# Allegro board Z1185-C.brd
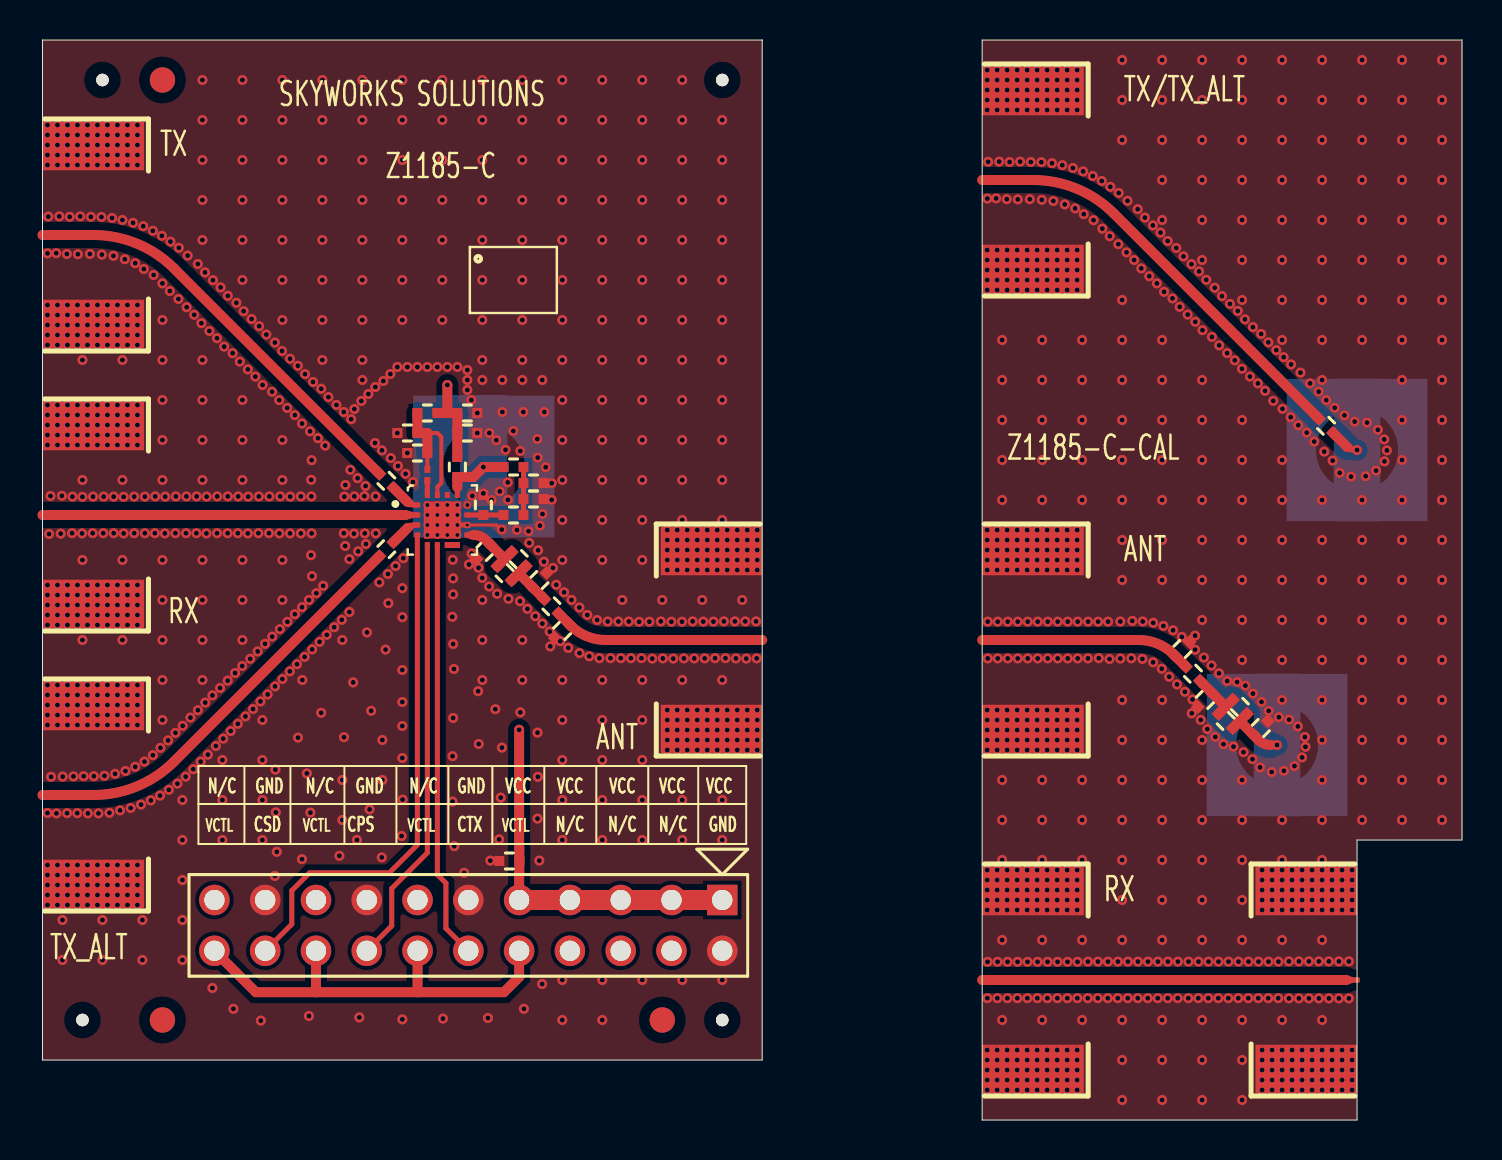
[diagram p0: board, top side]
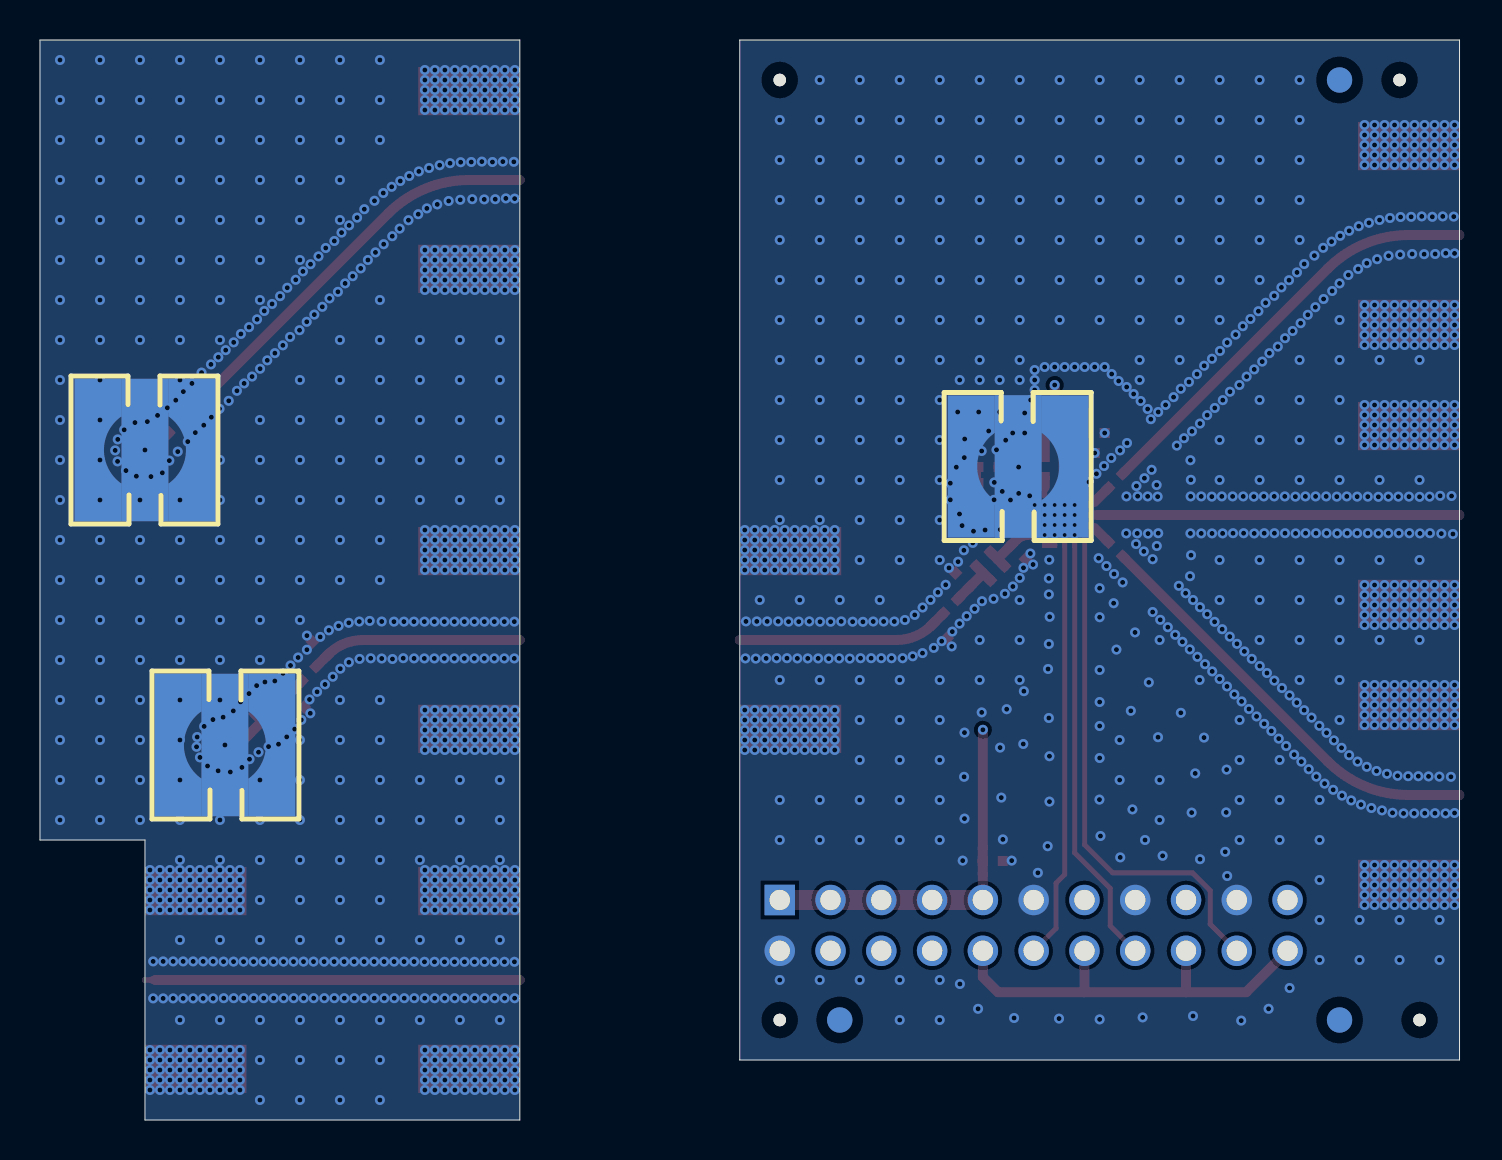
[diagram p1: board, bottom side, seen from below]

Outline 71 x 54 mm; copper layers: TOP, L2, L3, BOTTOM. Coordinates in mm from the lower left corner of the outline.
Outline path: 0,54 36,54 36,3 0,3 0,54 ; 47,54 47,0 65.75,0 65.75,14 71,14 71,54 47,54

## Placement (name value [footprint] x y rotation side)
C2  10nF  [CAP_SMD_0402_1M0MX0M5M_B]  18.25 34.35 180 top
C3  33pF  [CAP_SMD_0402_1M0MX0M5M_B]  21.25 34.35 180 top
C4  4.7uF  [CAP_SMD_0402_1M0MX0M5M_B]  23.35 12.95 0 top
C5  82pF  [CAP_SMD_0402_1M0MX0M5M_B]  18.75 33.35 180 top
C7  DNI  [CAP_SMD_0402_1M0MX0M5M_B]  24.56 31.05 0 top
C8  10pF  [CAP_SMD_0402_1M0MX0M5M_B]  24.56 31.85 0 top
C9  2.4pF  [CAP_SMD_0402_1M0MX0M5M_B]  22.05 30.75 90 top
C10  2.2pF  [CAP_SMD_0402_1M0MX0M5M_B]  24.86 27 45 top
C11  DNI  [CAP_SMD_0402_1M0MX0M5M_B]  58.14 21 225 top
C12  DNI  [CAP_SMD_0402_1M0MX0M5M_B]  22.06 28.4 225 top
C13  DNI  [CAP_SMD_0402_1M0MX0M5M_B]  25.98 24.45 225 top
C14  1.5pF  [CAP_SMD_0402_1M0MX0M5M_B]  23.11 27.34 315 top
C15  DNI  [CAP_SMD_0402_1M0MX0M5M_B]  60.94 19.6 45 top
C16  DNI  [CAP_SMD_0402_1M0MX0M5M_B]  57.02 23.55 45 top
C17  DNI  [CAP_SMD_0402_1M0MX0M5M_B]  59.18 19.95 135 top
C18  1nF  [CAP_SMD_0402_1M0MX0M5M_B]  21.25 35.35 180 top
FB1  0R  [IND_SMD_0402_1M0MX0M5M_B]  19.25 35.35 180 top
J1  SMA  [SMA_END_B]  0 30.25 180 top
J2  SMA  [SMA_END_B]  0 44.25 180 top
J3  SMA  [SMA_END_B]  36 24 0 top
J4  DNI  [CONN_AMP_132134_10_V2]  22.08 32.67 180 bottom
J5  SMA  [SMA_END_B]  0 16.25 180 top
J6  SMA  [SMA_END_B]  47 47 180 top
J7  SMA  [SMA_END_B]  47 7 180 top
J9  AMP  [CONN_AMP_132134_10_V2]  65.75 33.5 180 bottom
J10  SMA  [SMA_END_B]  65.75 7 0 top
J12  AMP  [CONN_AMP_132134_10_V2]  61.75 18.75 0 bottom
J13  SMA  [SMA_END_B]  47 24 180 top
L1  6.8nH  [IND_SMD_0402_1M0MX0M5M_B]  20.75 32.65 270 top
L2  0.6nH  [IND_SMD_0201_0M6MX0M3M_B]  19.25 32.25 270 top
L3  2.4nH  [IND_SMD_0402_1M0MX0M5M_B]  23.56 32.65 180 top
L4  7.5nH  [IND_SMD_0402_1M0MX0M5M_B]  23.56 30.25 180 top
L5  5.6nH  [IND_SMD_0402_1M0MX0M5M_B]  23.82 28.05 135 top
L6  5.6nH  [IND_SMD_0402_1M0MX0M5M_B]  25.46 25.68 135 top
L7  DNI  [IND_SMD_0402_1M0MX0M5M_B]  59.89 20.66 315 top
L8  DNI  [IND_SMD_0402_1M0MX0M5M_B]  57.54 22.32 315 top
NOREF  -  []  0 54 0 top
NOREF#2  -  []  82.78 -3.18 0 top
NOREF#3  -  [unnamed#2]  34 5 0 top
NOREF#4  -  []  -27.22 -24.19 0 top
NOREF#5  -  []  90.78 11.82 0 top
NOREF#6  -  [unnamed#2]  34 52 0 top
NOREF#7  -  [unnamed#2]  31 5 0 top
NOREF#8  -  []  0 3 90 top
NOREF#9  -  []  47 54 0 top
NOREF#10  -  [unnamed#2]  6 52 0 top
NOREF#11  -  []  47 0 0 top
NOREF#12  -  []  -42.87 -91.91 0 top
NOREF#13  -  []  65.75 0 90 top
NOREF#14  -  [unnamed#2]  6 5 0 top
NOREF#15  -  []  71 14 90 top
NOREF#16  -  [unnamed#2]  2 5 0 top
NOREF#17  -  [unnamed#2]  3 52 0 top
NOREF#18  -  []  26.32 60.56 0 top
NOREF#19  -  [unnamed#2]  31 5 180 bottom
NOREF#20  -  [unnamed#2]  6 52 180 bottom
NOREF#21  -  [unnamed#2]  6 5 180 bottom
P1  HEADER 11X2  [HDR_THRU_22P_11X2_100_ST_M]  34 11 180 top
R1  0R  [RES_SMD_0402_1M0MX0M5M_B]  17.2 31.96 135 top
R2  DNI  [RES_SMD_0402_1M0MX0M5M_B]  17.2 28.54 225 top
R4  DNI  [RES_SMD_0402_1M0MX0M5M_B]  64.2 34.71 135 top
U1  SKY66423-11  [SP01-D577-A]  20 30 0 top

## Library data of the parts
C2-C5 C7-C18 = CAP_NP
FB1 = FERRITE BEAD
J1-J3 J5-J7 J10 J13 = SMA_3pin
J4 J9 J12 = SMA_3
L1 L2 = IND_7
L3 = IND_1
L4 = IND_0
L5-L8 = IND_2
P1 = HEADER 11X2
R1 R2 R4 = RESISTOR
U1 = SKY13717_1

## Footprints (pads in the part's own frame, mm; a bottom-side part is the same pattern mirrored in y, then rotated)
CAP_SMD_0402_1M0MX0M5M_B
  rect 0.5x0.5 smd: 1(-0.5,0) 2(0.5,0)
CONN_AMP_132134_10_V2
  round 1.73 smd: 1(0,0)
  custom 0.588x0.588 smd: 2(0,0) 3(0,0)
HDR_THRU_22P_11X2_100_ST_M
  rect 1.524x1.524 hole 1.016: 1(0,0)
  round 1.524 hole 1.016: 2(0,2.54) 3(2.54,0) 4(2.54,2.54) 5(5.08,0) 6(5.08,2.54) 7(7.62,0) 8(7.62,2.54) 9(10.16,0) 10(10.16,2.54) 11(12.7,0) 12(12.7,2.54) 13(15.24,0) 14(15.24,2.54) 15(17.78,0) 16(17.78,2.54) 17(20.32,0) 18(20.32,2.54) 19(22.86,0) 20(22.86,2.54) 21(25.4,0) 22(25.4,2.54)
IND_SMD_0201_0M6MX0M3M_B
  rect 0.35x0.3 smd: 1(-0.28,0) 2(0.28,0)
IND_SMD_0402_1M0MX0M5M_B
  rect 0.5x0.5 smd: 1(-0.5,0) 2(0.5,0)
RES_SMD_0402_1M0MX0M5M_B
  rect 0.5x0.5 smd: 1(-0.5,0) 2(0.5,0)
SMA_END_B
  rect 0.249x0.249 smd: 1(0,0)
  rect 5.08x2.413 smd: 2(-2.54,4.445) 3(-2.54,-4.445)
SP01-D577-A
  rect 0.3x0.25 smd: 1(-1.25,0.75) 2(-1.25,0.25) 3(-1.25,-0.25) 4(-1.25,-0.75) 9(1.25,-0.75) 10(1.25,-0.25) 11(1.25,0.25) 12(1.25,0.75)
  rect 0.25x0.3 smd: 5(-0.75,-1.25) 6(-0.25,-1.25) 7(0.25,-1.25) 8(0.75,-1.25) 13(0.75,1.25) 14(0.25,1.25) 15(-0.25,1.25) 16(-0.75,1.25)
  rect 1.85x1.85 smd: 17(0,0)
unnamed#2
  round 0.625 hole 1.42 unplated: (0,0)

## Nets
GND: C2.2 C3.1 C4.1 C5.2 C7.2 C8.2 C9.2 C10.2 C11.2 C12.2 C13.2 C15.2 C16.2 C18.1 J1.2(GND_SIGNAL#2) J1.3(GND_SIGNAL#3) J2.2(GND_SIGNAL#2) J2.3(GND_SIGNAL#3) J3.2(GND_SIGNAL#2) J3.3(GND_SIGNAL#3) J4.2 J4.3 J5.2(GND_SIGNAL#2) J5.3(GND_SIGNAL#3) J6.2(GND_SIGNAL#2) J6.3(GND_SIGNAL#3) J7.2(GND_SIGNAL#2) J7.3(GND_SIGNAL#3) J9.2 J9.3 J10.2(GND_SIGNAL#2) J10.3(GND_SIGNAL#3) J12.2 J12.3 J13.2(GND_SIGNAL#2) J13.3(GND_SIGNAL#3) P1.2 P1.11 P1.15 P1.19 U1.10(GND_10) U1.12(GND_12) U1.17(EPAD)
VCC: C3.2 C4.2 C18.2 FB1.1 L1.1 P1.1 P1.3 P1.5 P1.7 P1.9
VCC_10: C2.1 C5.1 FB1.2 L2.1 U1.15(VCC0)
VCC_CONT: P1.10 P1.14 P1.18 P1.22
ANT: C13.1 J3.1(SIG) L6.1
ANT_9: C12.1 C14.1 L5.2 U1.9(ANT)
CPS: P1.16 U1.5(CPS)
CSD: P1.20 U1.4(CSD)
CTX: P1.12 U1.6(CTX)
P1_4_NC: P1.4
P1_6_NC: P1.6
P1_8_NC: P1.8
P1_13_NC: P1.13
P1_17_NC: P1.17
P1_21_NC: P1.21
PA_OUT: J4.1(RF) L1.2 L3.2 U1.13(PA_OUT)
RX: J1.1(SIG) U1.2(RX)
TX: R1.1 U1.1(TX)
TXALT: R2.1 U1.3(TX_ALT)
N17610851: J2.1(SIG) R1.2
N17610982: C7.1 C8.1 L3.1 L4.1
N17611082: C9.1 L4.2 U1.11(TX_IN)
N17611094: C10.1 C14.2 L5.1 L6.2
N17611136: U1.7(LNA_IN) U1.8(RX_FLT)
N17611154: L2.2 U1.16(VCC1)
N17611175: J5.1(SIG) R2.2
N17617542: J6.1(SIG) R4.2
N17617544: J7.1(SIG) J10.1(SIG)
N17617677: J9.1(RF) R4.1
N17626822: C11.1 C17.2 L7.1 L8.2
N17626830: C16.1 J13.1(SIG) L8.1
N17626834: C15.1 C17.1 J12.1(RF) L7.2

Pads without a net: U1 14

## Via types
v1: diameter 0.5, hole 0.25, TOP to BOTTOM, 1870 vias
v2: diameter 0.4, hole 0.2, TOP to BOTTOM, 17 vias
v3: diameter 0.35, hole 0.15, TOP to BOTTOM, 1 via

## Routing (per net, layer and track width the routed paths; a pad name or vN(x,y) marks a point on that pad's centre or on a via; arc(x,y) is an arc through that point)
GND: length 2.7
  TOP w0.15: v3(21.25,29.75) 22.7,29.75 22.9,29.55
  TOP w0.5: v1(35.75,19) v1(35.25,19) v1(34.75,19)
  vias: v1(0.25,49.75) v1(0.25,49.25) v1(0.25,48.75) v1(0.25,48.25) v1(0.25,47.75) v1(0.29,45.17) v1(0.25,43.33) v1(0.25,40.75) v1(0.25,40.25) v1(0.25,39.75) v1(0.25,39.25) v1(0.25,38.75) v1(0.25,35.75) v1(0.25,35.25) v1(0.25,34.75) v1(0.25,34.25) v1(0.25,33.75) v1(0.25,26.75) v1(0.25,26.25) v1(0.25,25.75) v1(0.25,25.25) v1(0.25,24.75) v1(0.25,21.75) v1(0.25,21.25) v1(0.25,20.75) v1(0.25,20.25) v1(0.25,19.75) v1(0.25,15.35) v1(0.25,12.75) v1(0.25,12.25) v1(0.25,11.75) v1(0.25,11.25) v1(0.25,10.75) v1(0.4,31.2) v1(0.33,29.3) v1(0.43,17.16) v1(0.69,43.34) v1(0.75,49.75) v1(0.75,49.25) v1(0.75,48.75) v1(0.75,48.25) v1(0.75,47.75) v1(0.75,40.75) v1(0.75,40.25) v1(0.75,39.75) v1(0.75,39.25) v1(0.75,38.75) v1(0.75,35.75) v1(0.75,35.25) v1(0.75,34.75) v1(0.75,34.25) v1(0.75,33.75) v1(0.75,26.75) v1(0.75,26.25) v1(0.75,25.75) v1(0.75,25.25) v1(0.75,24.75) v1(0.75,21.75) v1(0.75,21.25) v1(0.75,20.75) v1(0.75,20.25) v1(0.75,19.75) v1(0.7,15.33) v1(0.75,12.75) v1(0.75,12.25) v1(0.75,11.75) v1(0.75,11.25) v1(0.75,10.75) v1(0.84,45.18) v1(0.97,31.21) v1(0.91,29.32) v1(1,10) v1(1,8) v1(1.01,17.17) v1(1.25,49.75) v1(1.25,49.25) v1(1.25,48.75) v1(1.25,48.25) v1(1.25,47.75) v1(1.22,43.3) v1(1.25,40.75) v1(1.25,40.25) v1(1.25,39.75) v1(1.25,39.25) v1(1.25,38.75) v1(1.25,35.75) v1(1.25,35.25) v1(1.25,34.75) v1(1.25,34.25) v1(1.25,33.75) v1(1.25,26.75) v1(1.25,26.25) v1(1.25,25.75) v1(1.25,25.25) v1(1.25,24.75) v1(1.25,21.75) v1(1.25,21.25) v1(1.25,20.75) v1(1.25,20.25) v1(1.25,19.75) v1(1.23,15.34) v1(1.25,12.75) v1(1.25,12.25) v1(1.25,11.75) v1(1.25,11.25) v1(1.25,10.75) v1(1.36,45.16) v1(1.5,31.17) v1(1.48,29.34) v1(1.55,17.18) v1(1.75,49.75) v1(1.75,49.25) v1(1.75,48.75) v1(1.75,48.25) v1(1.75,47.75) v1(1.77,43.29) v1(1.75,40.75) v1(1.75,40.25) v1(1.75,39.75) v1(1.75,39.25) v1(1.75,38.75) v1(1.75,35.75) v1(1.75,35.25) v1(1.75,34.75) v1(1.75,34.25) v1(1.75,33.75) v1(1.75,26.75) v1(1.75,26.25) v1(1.75,25.75) v1(1.75,25.25) v1(1.75,24.75) v1(1.75,21.75) v1(1.75,21.25) v1(1.75,20.75) v1(1.75,20.25) v1(1.75,19.75) v1(1.74,15.34) v1(1.75,12.75) v1(1.75,12.25) v1(1.75,11.75) v1(1.75,11.25) v1(1.75,10.75) v1(1.89,45.18) v1(2,38) v1(2,32) v1(2,31.16) v1(1.98,29.33) v1(2,28) v1(2,24) v1(2.06,17.19) v1(2.25,49.75) v1(2.25,49.25) v1(2.25,48.75) v1(2.25,48.25) v1(2.25,47.75) v1(2.25,40.75) v1(2.25,40.25) v1(2.25,39.75) v1(2.25,39.25) v1(2.25,38.75) v1(2.25,35.75) v1(2.25,35.25) v1(2.25,34.75) v1(2.25,34.25) v1(2.25,33.75) v1(2.25,26.75) v1(2.25,26.25) v1(2.25,25.75) v1(2.25,25.25) v1(2.25,24.75) v1(2.25,21.75) v1(2.25,21.25) v1(2.25,20.75) v1(2.25,20.25) v1(2.25,19.75) v1(2.27,15.33) v1(2.25,12.75) v1(2.25,12.25) v1(2.25,11.75) v1(2.25,11.25) v1(2.25,10.75) v1(2.37,43.3) v1(2.42,45.16) v1(2.53,31.17) v1(2.51,29.34) v1(2.57,17.19) v1(2.75,49.75) v1(2.75,49.25) v1(2.75,48.75) v1(2.75,48.25) v1(2.75,47.75) v1(2.75,40.75) v1(2.75,40.25) v1(2.75,39.75) v1(2.75,39.25) v1(2.75,38.75) v1(2.75,35.75) v1(2.75,35.25) v1(2.75,34.75) v1(2.75,34.25) v1(2.75,33.75) v1(2.75,26.75) v1(2.75,26.25) v1(2.75,25.75) v1(2.75,25.25) v1(2.75,24.75) v1(2.75,21.75) v1(2.75,21.25) v1(2.75,20.75) v1(2.75,20.25) v1(2.75,19.75) v1(2.8,15.33) v1(2.75,12.75) v1(2.75,12.25) v1(2.75,11.75) v1(2.75,11.25) v1(2.75,10.75) v1(2.95,45.15) v1(2.97,43.27) v1(3,10) v1(3,8) v1(3.06,31.17) v1(3.04,29.34) v1(3.1,17.21) v1(3.25,49.75) v1(3.25,49.25) v1(3.25,48.75) v1(3.25,48.25) v1(3.25,47.75) v1(3.25,40.75) v1(3.25,40.25) v1(3.25,39.75) v1(3.25,39.25) v1(3.25,38.75) v1(3.25,35.75) v1(3.25,35.25) v1(3.25,34.75) v1(3.25,34.25) v1(3.25,33.75) v1(3.25,26.75) v1(3.25,26.25) v1(3.25,25.75) v1(3.25,25.25) v1(3.25,24.75) v1(3.25,21.75) v1(3.25,21.25) v1(3.25,20.75) v1(3.25,20.25) v1(3.25,19.75) v1(3.25,12.75) v1(3.25,12.25) v1(3.25,11.75) v1(3.25,11.25) v1(3.25,10.75) v1(3.35,15.36) v1(3.48,45.1) v1(3.55,43.21) v1(3.56,31.17) v1(3.56,29.34) v1(3.63,17.31) v1(3.75,49.75) v1(3.75,49.25) v1(3.75,48.75) v1(3.75,48.25) v1(3.75,47.75) v1(3.75,40.75) v1(3.75,40.25) v1(3.75,39.75) v1(3.75,39.25) v1(3.75,38.75) v1(3.75,35.75) v1(3.75,35.25) v1(3.75,34.75) v1(3.75,34.25) v1(3.75,33.75) v1(3.75,26.75) v1(3.75,26.25) v1(3.75,25.75) v1(3.75,25.25) v1(3.75,24.75) v1(3.75,21.75) v1(3.75,21.25) v1(3.75,20.75) v1(3.75,20.25) v1(3.75,19.75) v1(3.75,12.75) v1(3.75,12.25) v1(3.75,11.75) v1(3.75,11.25) v1(3.75,10.75) v1(3.88,15.48) v1(4,45) v1(4,38) v1(4,32) v1(4,28) v1(4,24) v1(4.06,31.16) v1(4.06,29.33) v1(4.12,43.04) v1(4.15,17.45) v1(4.25,49.75) v1(4.25,49.25) v1(4.25,48.75) v1(4.25,48.25) v1(4.25,47.75) v1(4.25,40.75) v1(4.25,40.25) v1(4.25,39.75) v1(4.25,39.25) v1(4.25,38.75) v1(4.25,35.75) v1(4.25,35.25) v1(4.25,34.75) v1(4.25,34.25) v1(4.25,33.75) v1(4.25,26.75) v1(4.25,26.25) v1(4.25,25.75) v1(4.25,25.25) v1(4.25,24.75) v1(4.25,21.75) v1(4.25,21.25) v1(4.25,20.75) v1(4.25,20.25) v1(4.25,19.75) v1(4.25,12.75) v1(4.25,12.25) v1(4.25,11.75) v1(4.25,11.25) v1(4.25,10.75) v1(4.41,15.6) v1(4.53,44.86) v1(4.59,31.17) v1(4.59,29.34) v1(4.64,42.84) v1(4.64,17.66) v1(4.75,49.75) v1(4.75,49.25) v1(4.75,48.75) v1(4.75,48.25) v1(4.75,47.75) v1(4.75,40.75) v1(4.75,40.25) v1(4.75,39.75) v1(4.75,39.25) v1(4.75,38.75) v1(4.75,35.75) v1(4.75,35.25) v1(4.75,34.75) v1(4.75,34.25) v1(4.75,33.75) v1(4.75,26.75) v1(4.75,26.25) v1(4.75,25.75) v1(4.75,25.25) v1(4.75,24.75) v1(4.75,21.75) v1(4.75,21.25) v1(4.75,20.75) v1(4.75,20.25) v1(4.75,19.75) v1(4.75,12.75) v1(4.75,12.25) v1(4.75,11.75) v1(4.75,11.25) v1(4.75,10.75) v1(4.93,15.77) v1(5,10) v1(5,8) v1(5.04,44.69) v1(5.07,42.55) v1(5.12,31.17) v1(5.12,29.34) v1(5.1,17.92) v1(5.42,15.98) v1(5.52,44.46) v1(5.56,42.25) v1(5.52,18.24) v1(5.64,31.18) v1(5.62,29.34) v1(5.88,16.22) v1(5.97,44.21) v1(6,41.83) v1(6,40) v1(6,38) v1(6,36) v1(6,34) v1(6,32) v1(6,28) v1(6,26) v1(6,24) v1(6,22) v1(6,20) v1(5.9,18.61) v1(6.14,31.17) v1(6.12,29.33) v1(6.28,18.98) v1(6.4,43.92) v1(6.37,41.45) v1(6.32,16.51) v1(6.67,31.18) v1(6.65,29.34) v1(6.65,19.36) v1(6.8,41.05) v1(6.75,16.82) v1(6.82,43.61) v1(7,16) v1(7,14) v1(7,12) v1(7,10) v1(7,8) v1(7.01,19.71) v1(7.2,31.18) v1(7.18,29.34) v1(7.16,17.17) v1(7.26,43.22) v1(7.21,40.64) v1(7.4,20.12) v1(7.59,40.26) v1(7.54,17.54) v1(7.7,29.34) v1(7.77,42.8) v1(7.71,31.18) v1(7.77,20.49) v1(8,52) v1(8,50) v1(8,48) v1(8,46) v1(8,44) v1(7.95,39.84) v1(8,38) v1(8,36) v1(8,34) v1(8,32) v1(8,28) v1(8,26) v1(8,24) v1(8,22) v1(7.91,17.92) v1(8.13,42.38) v1(8.2,29.33) v1(8.14,20.87) v1(8.21,31.17) v1(8.27,18.27) v1(8.35,39.45) v1(8.53,41.99) v1(8.5,21.23) v1(8.5,6.6) v1(8.67,18.7) v1(8.73,39.09) v1(8.74,31.18) v1(8.73,29.34) v1(8.88,21.6) v1(8.91,41.63) v1(9,18) v1(9,16) v1(9,14) v1(9.09,38.67) v1(9.04,19.07) v1(9.27,41.21) v1(9.27,31.18) v1(9.26,29.34) v1(9.26,21.97) v1(9.41,19.45) v1(9.51,38.34) v1(9.55,5.56) v1(9.7,40.86) v1(9.63,22.35) v1(9.79,31.18) v1(9.77,29.34) v1(9.77,19.81) v1(9.87,37.92) v1(10,52) v1(10,50) v1(10,48) v1(10,46) v1(10,44) v1(10,42) v1(10,36) v1(10,34) v1(10,32) v1(10,28) v1(10,26) v1(10,24) v1(9.99,22.7) v1(10.06,40.44) v1(10.15,20.18) v1(10.27,37.53) v1(10.29,31.17) v1(10.27,29.33) v1(10.39,23.06) v1(10.46,40.05) v1(10.53,20.55) v1(10.65,37.17) v1(10.8,29.34) v1(10.76,23.43) v1(10.84,39.69) v1(10.82,31.18) v1(10.9,20.93) v1(11,20) v1(11,18) v1(11,16) v1(11,14) v1(10.92,4.97) v1(11.01,36.75) v1(11.2,39.27) v1(11.13,23.81) v1(11.26,21.28) v1(11.35,31.18) v1(11.33,29.34) v1(11.48,36.41) v1(11.49,24.17) v1(11.62,38.87) v1(11.63,21.68) v1(11.65,17.52) v1(11.67,15.38) v1(11.62,12.2) v1(11.72,13.41) v1(11.84,35.99) v1(11.89,31.18) v1(11.85,29.33) v1(11.87,24.54) v1(12,52) v1(12,50) v1(12,48) v1(12,46) v1(12,44) v1(12,42) v1(12,40) v1(11.98,38.45) v1(12,34) v1(12,32) v1(12,28) v1(12,26) v1(12,22.05) v1(12.24,35.6) v1(12.25,24.91) v1(12.38,38.06) v1(12.39,31.17) v1(12.38,29.33) v1(12.37,22.43) v1(12.62,35.24) v1(12.62,25.29) v1(12.77,37.71) v1(12.73,22.79) v1(12.78,19.12) v1(12.98,34.82) v1(12.92,31.18) v1(12.92,29.33) v1(12.98,25.64) v1(13,22) v1(12.98,13.04) v1(13.13,37.29) v1(13.11,23.16) v1(13.22,17.33) v1(13.38,34.43) v1(13.33,26) v1(13.4,15.37) v1(13.33,5.2) v1(13.46,32.99) v1(13.44,32.01) v1(13.45,31.18) v1(13.46,29.33) v1(13.43,28.24) v1(13.48,27.19) v1(13.49,23.53) v1(13.53,36.9) v1(13.78,34.09) v1(13.7,26.34) v1(13.86,23.91) v1(14,52) v1(14,50) v1(14,48) v1(14,46) v1(14,44) v1(14,42) v1(14,40) v1(14,38) v1(13.94,36.56) v1(13.94,20.36) v1(14.04,26.71) v1(14.14,33.72) v1(14.22,24.26) v1(14.3,36.14) v1(14.59,24.64) v1(14.7,35.75) v1(14.85,13.21) v1(14.97,25.01) v1(15,24) v1(15,17) v1(15,15) v1(15.07,35.4) v1(15.07,29.34) v1(15.08,19.14) v1(15.15,31.75) v1(15.1,31.17) v1(15.14,28.7) v1(15.4,32.51) v1(15.35,28.04) v1(15.35,25.4) v1(15.44,35.04) v1(15.58,29.32) v1(15.54,21.88) v1(15.6,35.55) v1(15.6,31.18) v1(15.76,32.09) v1(15.79,28.43) v1(15.73,14) v1(15.85,5.13) v1(16,52) v1(16,50) v1(16,48) v1(16,46) v1(16,44) v1(16,42) v1(16,40) v1(16,38) v1(16,37) v1(15.95,35.95) v1(16.16,31.7) v1(16.1,31.19) v1(16.12,29.33) v1(16.18,28.8) v1(16.3,36.3) v1(16.23,24.38) v1(16.36,15.53) v1(16.44,20.46) v1(16.65,36.65) v1(16.63,33.85) v1(16.66,31.18) v1(16.67,29.33) v1(16.85,26.88) v1(16.98,33.48) v1(17,19) v1(17,17) v1(16.97,13.13) v1(17.05,36.95) v1(17.16,23.52) v1(17.28,27.3) v1(17.3,25.84) v1(17.4,37.3) v1(17.42,33.1) v1(17.66,27.7) v1(17.75,37.65) v1(17.75,34.35) v1(17.78,32.7) v1(18,52) v1(18,50) v1(18,48) v1(18,46) v1(18,44) v1(18,42) v1(18,40) v1(18,26.59) v1(18,25.14) v1(18,22.5) v1(18,20.9) v1(18,19.7) v1(18,18.1) v1(17.96,14.2) v1(18,5.03) v1(18.05,28.09) v1(18.01,16.02) v1(18.16,32.31) v1(18.25,37.65) v1(18.25,33.35) v1(18.53,31.9) v1(18.75,37.65) v1(19.25,37.65) v1(19.75,37.65) v1(20,52) v1(20,50) v1(20,48) v1(20,46) v1(20,44) v1(20,42) v1(20,40) v1(20.03,5.07) v1(20.25,37.65) v1(20.52,28.01) v1(20.54,27.08) v1(20.54,26.28) v1(20.5,25.16) v1(20.54,23.8) v1(20.58,22.55) v1(20.54,20.1) v1(20.51,18.19) v1(20.51,15.92) v1(20.6,13.69) v1(20.75,37.65) v1(21.09,12.36) v1(21.25,37.5) v1(21.25,37) v1(21.25,36.5) v1(21.33,27.77) v1(21.45,36) v1(21.47,28.32) v1(21.5,31.21) v1(21.75,35.35) v1(21.75,34.35) v1(21.79,21.44) v1(21.81,27.61) v1(21.82,18.8) v1(22,52) v1(22,50) v1(22,48) v1(22,46) v1(22,44) v1(22,42) v1(22,40) v1(22,38) v1(22,37) v1(21.99,27.11) v1(22,26) v1(22,24) v1(22,22) v1(22.05,31.33) v1(22.28,5.1) v1(22.35,34.35) v1(22.34,26.68) v1(22.4,12.97) v1(22.46,31) v1(22.65,20.54) v1(22.7,33.99) v1(22.74,26.31) v1(22.87,31.43) v1(22.84,14.03) v1(23,37) v1(23,35.4) v1(22.97,29.52) v1(22.98,18.62) v1(22.92,16.12) v1(23.16,33.51) v1(23.27,31.88) v1(23.28,31.01) v1(23.3,26.06) v1(23.55,34.45) v1(23.73,29.5) v1(23.9,33.45) v1(23.88,25.94) v1(23.9,20.38) v1(24,52) v1(24,50) v1(24,48) v1(24,46) v1(24,44) v1(24,42) v1(24,40) v1(24,38) v1(24,37) v1(24,24) v1(24,22) v1(24.05,35.4) v1(24.08,5.56) v1(24.26,25.56) v1(24.31,29.44) v1(24.34,28.86) v1(24.65,25.19) v1(24.75,34.05) v1(24.77,33.12) v1(24.79,28.48) v1(24.76,19.37) v1(24.78,17.16) v1(24.76,15.07) v1(24.88,29.72) v1(24.85,12.97) v1(25,37) v1(24.99,6.8) v1(25.01,30.3) v1(25.08,27.91) v1(25.01,24.82) v1(25.1,35.4) v1(25.17,32.64) v1(25.37,24.42) v1(25.4,23.68) v1(25.47,31.84) v1(25.47,31.01) v1(25.53,27.61) v1(25.7,26.76) v1(25.9,23.94) v1(26,52) v1(26,50) v1(26,48) v1(26,46) v1(26,44) v1(26,42) v1(26,40) v1(26,38) v1(26,36) v1(26,34) v1(26,32) v1(26,30) v1(26,28) v1(26,22) v1(26,20) v1(26,18) v1(26,16) v1(26,14) v1(26,7) v1(26,5) v1(26.09,26.38) v1(26.3,23.61) v1(26.46,26) v1(26.85,25.62) v1(26.86,23.34) v1(27.25,25.25) v1(27.35,23.18) v1(27.74,25) v1(27.85,23.09) v1(28,52) v1(28,50) v1(28,48) v1(28,46) v1(28,44) v1(28,42) v1(28,40) v1(28,38) v1(28,36) v1(28,34) v1(28,32) v1(28,30) v1(28,28) v1(28,22) v1(28,20) v1(28,18) v1(28,16) v1(28,14) v1(28,7) v1(28,5) v1(28.27,24.93) v1(28.41,23.09) v1(28.8,24.93) v1(29,26) v1(28.92,23.09) v1(29.33,24.93) v1(29.43,23.09) v1(29.84,24.91) v1(30,52) v1(30,50) v1(30,48) v1(30,46) v1(30,44) v1(30,42) v1(30,40) v1(30,38) v1(30,36) v1(30,34) v1(30,32) v1(30,30) v1(30,28) v1(29.96,23.09) v1(30,22) v1(30,20) v1(30,18) v1(30,16) v1(30,14) v1(30,7) v1(30.36,24.91) v1(30.5,23.07) v1(31,26) v1(30.93,24.93) v1(31.03,23.08) v1(31.25,29.5) v1(31.25,29) v1(31.25,28.5) v1(31.25,28) v1(31.25,27.5) v1(31.25,20.5) v1(31.25,20) v1(31.25,19.5) v1(31.25,19) v1(31.25,18.5) v1(31.45,24.91) v1(31.55,23.07) v1(31.75,29.5) v1(31.75,29) v1(31.75,28.5) v1(31.75,28) v1(31.75,27.5) v1(31.75,20.5) v1(31.75,20) v1(31.75,19.5) v1(31.75,19) v1(31.75,18.5) v1(32,52) v1(32,50) v1(32,48) v1(32,46) v1(32,44) v1(32,42) v1(32,40) v1(32,38) v1(32,36) v1(32,34) v1(32,32) v1(32,30) v1(31.98,24.91) v1(32,22) v1(32,16) v1(32,14) v1(32,7) v1(32.08,23.08) v1(32.25,29.5) v1(32.25,29) v1(32.25,28.5) v1(32.25,28) v1(32.25,27.5) v1(32.25,20.5) v1(32.25,20) v1(32.25,19.5) v1(32.25,19) v1(32.25,18.5) v1(32.52,24.93) v1(32.6,23.08) v1(32.75,29.5) v1(32.75,29) v1(32.75,28.5) v1(32.75,28) v1(32.75,27.5) v1(32.75,20.5) v1(32.75,20) v1(32.75,19.5) v1(32.75,19) v1(32.75,18.5) v1(33,26) v1(33.05,24.92) v1(33.12,23.08) v1(33.25,29.5) v1(33.25,29) v1(33.25,28.5) v1(33.25,28) v1(33.25,27.5) v1(33.25,20.5) v1(33.25,20) v1(33.25,19.5) v1(33.25,19) v1(33.25,18.5) v1(33.56,24.92) v1(33.64,23.09) v1(33.75,29.5) v1(33.75,29) v1(33.75,28.5) v1(33.75,28) v1(33.75,27.5) v1(33.75,20.5) v1(33.75,20) v1(33.75,19.5) v1(33.75,19) v1(33.75,18.5) v1(34,50) v1(34,48) v1(34,46) v1(34,44) v1(34,42) v1(34,40) v1(34,38) v1(34,36) v1(34,34) v1(34,32) v1(34,30) v1(34,22) v1(34,16) v1(34,14) v1(34,7) v1(34.08,24.93) v1(34.16,23.09) v1(34.25,29.5) v1(34.25,29) v1(34.25,28.5) v1(34.25,28) v1(34.25,27.5) v1(34.25,20.5) v1(34.25,20) v1(34.25,19.5) v1(34.25,19) v1(34.25,18.5) v1(34.63,24.93) v1(34.68,23.08) v1(34.75,29.5) v1(34.75,29) v1(34.75,28.5) v1(34.75,28) v1(34.75,27.5) v1(34.75,20.5) v1(34.75,20) v1(34.75,19.5) v1(34.75,18.5) v1(35,26) v1(35.15,24.93) v1(35.2,23.07) v1(35.25,29.5) v1(35.25,29) v1(35.25,28.5) v1(35.25,28) v1(35.25,27.5) v1(35.25,20.5) v1(35.25,20) v1(35.25,19.5) v1(35.25,18.5) v1(35.69,24.93) v1(35.75,29.5) v1(35.75,29) v1(35.75,28.5) v1(35.75,28) v1(35.75,27.5) v1(35.72,23.08) v1(35.75,20.5) v1(35.75,20) v1(35.75,19.5) v1(35.75,18.5) v1(47.25,52.5) v1(47.25,52) v1(47.25,51.5) v1(47.25,51) v1(47.25,50.5) v1(47.26,46.07) v1(47.25,43.5) v1(47.25,43) v1(47.25,42.5) v1(47.25,42) v1(47.25,41.5) v1(47.25,29.5) v1(47.25,29) v1(47.25,28.5) v1(47.25,28) v1(47.25,27.5) v1(47.28,24.92) v1(47.28,23.08) v1(47.25,20.5) v1(47.25,20) v1(47.25,19.5) v1(47.25,19) v1(47.25,18.5) v1(47.25,12.5) v1(47.25,12) v1(47.25,11.5) v1(47.25,11) v1(47.25,10.5) v1(47.27,7.91) v1(47.26,6.09) v1(47.25,3.5) v1(47.25,3) v1(47.25,2.5) v1(47.25,2) v1(47.25,1.5) v1(47.3,47.91) v1(47.7,46.08) v1(47.75,52.5) v1(47.75,52) v1(47.75,51.5) v1(47.75,51) v1(47.75,50.5) v1(47.75,43.5) v1(47.75,43) v1(47.75,42.5) v1(47.75,42) v1(47.75,41.5) v1(47.75,29.5) v1(47.75,29) v1(47.75,28.5) v1(47.75,28) v1(47.75,27.5) v1(47.78,24.92) v1(47.78,23.08) v1(47.75,20.5) v1(47.75,20) v1(47.75,19.5) v1(47.75,19) v1(47.75,18.5) v1(47.75,12.5) v1(47.75,12) v1(47.75,11.5) v1(47.75,11) v1(47.75,10.5) v1(47.77,7.91) v1(47.76,6.09) v1(47.75,3.5) v1(47.75,3) v1(47.75,2.5) v1(47.75,2) v1(47.75,1.5) v1(47.85,47.92) v1(48,39) v1(48,37) v1(48,35) v1(48,33) v1(48,31) v1(48,17) v1(48,15) v1(48,13) v1(48,9) v1(48,5) v1(48.25,52.5) v1(48.25,52) v1(48.25,51.5) v1(48.25,51) v1(48.25,50.5) v1(48.23,46.04) v1(48.25,43.5) v1(48.25,43) v1(48.25,42.5) v1(48.25,42) v1(48.25,41.5) v1(48.25,29.5) v1(48.25,29) v1(48.25,28.5) v1(48.25,28) v1(48.25,27.5) v1(48.28,24.92) v1(48.28,23.08) v1(48.25,20.5) v1(48.25,20) v1(48.25,19.5) v1(48.25,19) v1(48.25,18.5) v1(48.25,12.5) v1(48.25,12) v1(48.25,11.5) v1(48.25,11) v1(48.25,10.5) v1(48.27,7.91) v1(48.26,6.09) v1(48.25,3.5) v1(48.25,3) v1(48.25,2.5) v1(48.25,2) v1(48.25,1.5) v1(48.37,47.9) v1(48.75,52.5) v1(48.75,52) v1(48.75,51.5) v1(48.75,51) v1(48.75,50.5) v1(48.78,46.03) v1(48.75,43.5) v1(48.75,43) v1(48.75,42.5) v1(48.75,42) v1(48.75,41.5) v1(48.75,29.5) v1(48.75,29) v1(48.75,28.5) v1(48.75,28) v1(48.75,27.5) v1(48.78,24.92) v1(48.78,23.08) v1(48.75,20.5) v1(48.75,20) v1(48.75,19.5) v1(48.75,19) v1(48.75,18.5) v1(48.75,12.5) v1(48.75,12) v1(48.75,11.5) v1(48.75,11) v1(48.75,10.5) v1(48.77,7.91) v1(48.76,6.09) v1(48.75,3.5) v1(48.75,3) v1(48.75,2.5) v1(48.75,2) v1(48.75,1.5) v1(48.9,47.92) v1(49.25,52.5) v1(49.25,52) v1(49.25,51.5) v1(49.25,51) v1(49.25,50.5) v1(49.25,43.5) v1(49.25,43) v1(49.25,42.5) v1(49.25,42) v1(49.25,41.5) v1(49.25,29.5) v1(49.25,29) v1(49.25,28.5) v1(49.25,28) v1(49.25,27.5) v1(49.28,24.92) v1(49.28,23.08) v1(49.25,20.5) v1(49.25,20) v1(49.25,19.5) v1(49.25,19) v1(49.25,18.5) v1(49.25,12.5) v1(49.25,12) v1(49.25,11.5) v1(49.25,11) v1(49.25,10.5) v1(49.27,7.91) v1(49.26,6.09) v1(49.25,3.5) v1(49.25,3) v1(49.25,2.5) v1(49.25,2) v1(49.25,1.5) v1(49.38,46.04) v1(49.43,47.9) v1(49.75,52.5) v1(49.75,52) v1(49.75,51.5) v1(49.75,51) v1(49.75,50.5) v1(49.75,43.5) v1(49.75,43) v1(49.75,42.5) v1(49.75,42) v1(49.75,41.5) v1(49.75,29.5) v1(49.75,29) v1(49.75,28.5) v1(49.75,28) v1(49.75,27.5) v1(49.78,24.92) v1(49.78,23.08) v1(49.75,20.5) v1(49.75,20) v1(49.75,19.5) v1(49.75,19) v1(49.75,18.5) v1(49.75,12.5) v1(49.75,12) v1(49.75,11.5) v1(49.75,11) v1(49.75,10.5) v1(49.77,7.91) v1(49.76,6.09) v1(49.75,3.5) v1(49.75,3) v1(49.75,2.5) v1(49.75,2) v1(49.75,1.5) v1(49.96,47.89) v1(49.98,46.01) v1(50,39) v1(50,37) v1(50,35) v1(50,33) v1(50,31) v1(50,17) v1(50,15) v1(50,13) v1(50,9) v1(50,5) v1(50.25,52.5) v1(50.25,52) v1(50.25,51.5) v1(50.25,51) v1(50.25,50.5) v1(50.25,43.5) v1(50.25,43) v1(50.25,42.5) v1(50.25,42) v1(50.25,41.5) v1(50.25,29.5) v1(50.25,29) v1(50.25,28.5) v1(50.25,28) v1(50.25,27.5) v1(50.28,24.92) v1(50.28,23.08) v1(50.25,20.5) v1(50.25,20) v1(50.25,19.5) v1(50.25,19) v1(50.25,18.5) v1(50.25,12.5) v1(50.25,12) v1(50.25,11.5) v1(50.25,11) v1(50.25,10.5) v1(50.27,7.91) v1(50.26,6.09) v1(50.25,3.5) v1(50.25,3) v1(50.25,2.5) v1(50.25,2) v1(50.25,1.5) v1(50.49,47.84) v1(50.56,45.95) v1(50.75,52.5) v1(50.75,52) v1(50.75,51.5) v1(50.75,51) v1(50.75,50.5) v1(50.75,43.5) v1(50.75,43) v1(50.75,42.5) v1(50.75,42) v1(50.75,41.5) v1(50.75,29.5) v1(50.75,29) v1(50.75,28.5) v1(50.75,28) v1(50.75,27.5) v1(50.78,24.92) v1(50.78,23.08) v1(50.75,20.5) v1(50.75,20) v1(50.75,19.5) v1(50.75,19) v1(50.75,18.5) v1(50.75,12.5) v1(50.75,12) v1(50.75,11.5) v1(50.75,11) v1(50.75,10.5) v1(50.77,7.91) v1(50.76,6.09) v1(50.75,3.5) v1(50.75,3) v1(50.75,2.5) v1(50.75,2) v1(50.75,1.5) v1(51.01,47.74) v1(51.13,45.78) v1(51.25,52.5) v1(51.25,52) v1(51.25,51.5) v1(51.25,51) v1(51.25,50.5) v1(51.25,43.5) v1(51.25,43) v1(51.25,42.5) v1(51.25,42) v1(51.25,41.5) v1(51.25,29.5) v1(51.25,29) v1(51.25,28.5) v1(51.25,28) v1(51.25,27.5) v1(51.28,24.92) v1(51.28,23.08) v1(51.25,20.5) v1(51.25,20) v1(51.25,19.5) v1(51.25,19) v1(51.25,18.5) v1(51.25,12.5) v1(51.25,12) v1(51.25,11.5) v1(51.25,11) v1(51.25,10.5) v1(51.27,7.91) v1(51.26,6.09) v1(51.25,3.5) v1(51.25,3) v1(51.25,2.5) v1(51.25,2) v1(51.25,1.5) v1(51.54,47.6) v1(51.65,45.58) v1(51.75,52.5) v1(51.75,52) v1(51.75,51.5) v1(51.75,51) v1(51.75,50.5) v1(51.75,43.5) v1(51.75,43) v1(51.75,42.5) v1(51.75,42) v1(51.75,41.5) v1(51.75,29.5) v1(51.75,29) v1(51.75,28.5) v1(51.75,28) v1(51.75,27.5) v1(51.78,24.92) v1(51.78,23.08) v1(51.75,20.5) v1(51.75,20) v1(51.75,19.5) v1(51.75,19) v1(51.75,18.5) v1(51.75,12.5) v1(51.75,12) v1(51.75,11.5) v1(51.75,11) v1(51.75,10.5) v1(51.77,7.91) v1(51.76,6.09) v1(51.75,3.5) v1(51.75,3) v1(51.75,2.5) v1(51.75,2) v1(51.75,1.5) v1(52,39) v1(52,37) v1(52,35) v1(52,33) v1(52,31) v1(52,17) v1(52,15) v1(52,13) v1(52,9) v1(52,5) v1(52.05,47.43) v1(52.08,45.29) v1(52.3,24.92) v1(52.29,23.08) v1(52.29,7.92) v1(52.28,6.09) v1(52.53,47.2) v1(52.57,44.99) v1(52.8,24.92) v1(52.79,7.92) v1(52.78,6.09) v1(52.83,23.09) v1(52.98,46.95) v1(53.01,44.57) v1(53.3,24.92) v1(53.29,7.92) v1(53.28,6.09) v1(53.38,44.19) v1(53.37,23.05) v1(53.41,46.66) v1(53.79,7.92) v1(53.78,6.09) v1(53.83,46.35) v1(53.81,43.79) v1(54,53) v1(54,51) v1(54,49) v1(54,41) v1(54,39) v1(54,37) v1(54,35) v1(54,33) v1(54,31) v1(54,29) v1(54,27) v1(53.91,24.93) v1(53.91,23.07) v1(54,21) v1(54,19) v1(54,17) v1(54,15) v1(54,13) v1(54,11) v1(54,9) v1(54,5) v1(54,3) v1(54,1) v1(54.27,45.96) v1(54.22,43.38) v1(54.29,7.92) v1(54.28,6.09) v1(54.46,23.09) v1(54.6,43) v1(54.51,24.95) v1(54.78,45.54) v1(54.79,7.92) v1(54.78,6.09) v1(54.96,42.58) v1(55.03,24.93) v1(55.02,23.05) v1(55.14,45.12) v1(55.29,7.92) v1(55.28,6.09) v1(55.36,42.19) v1(55.54,44.73) v1(55.55,24.86) v1(55.55,22.88) v1(55.74,41.83) v1(55.79,7.92) v1(55.78,6.09) v1(56,53) v1(56,51) v1(56,49) v1(56,47) v1(56,45) v1(55.92,44.37) v1(56,39) v1(56,37) v1(56,35) v1(56,33) v1(56,31) v1(56,29) v1(56,27) v1(55.98,22.57) v1(56,21) v1(56,19) v1(56,17) v1(56,15) v1(56,13) v1(56,11) v1(56,9) v1(56,5) v1(56,3) v1(56,1) v1(56.1,41.41) v1(56.06,24.7) v1(56.28,43.95) v1(56.29,7.92) v1(56.28,6.09) v1(56.36,22.16) v1(56.52,41.08) v1(56.55,24.48) v1(56.71,43.6) v1(56.74,21.78) v1(56.79,7.92) v1(56.78,6.09) v1(56.88,40.66) v1(56.98,24.16) v1(57.07,43.18) v1(57.14,21.41) v1(57.28,40.27) v1(57.32,7.92) v1(57.31,6.09) v1(57.47,42.79) v1(57.48,20.34) v1(57.52,21.02) v1(57.66,39.91) v1(57.65,24.22) v1(57.65,23.52) v1(57.85,42.43) v1(57.82,7.92) v1(57.81,6.09) v1(58,53) v1(58,51) v1(58,49) v1(58,47) v1(58,45) v1(58,43) v1(58,37) v1(58,35) v1(58,33) v1(58,31) v1(58,29) v1(58,27) v1(58,25) v1(57.93,20) v1(58,19) v1(58,17) v1(58,15) v1(58,13) v1(58,11) v1(58,9) v1(58,5) v1(58,3) v1(58,1) v1(58.02,39.49) v1(58.09,23.12) v1(58.21,42.01) v1(58.26,19.55) v1(58.32,7.92) v1(58.31,6.09) v1(58.49,39.15) v1(58.47,22.73) v1(58.63,41.61) v1(58.66,19.16) v1(58.85,38.73) v1(58.84,22.34) v1(58.82,7.92) v1(58.81,6.09) v1(58.99,41.19) v1(59.07,18.79) v1(59.25,38.34) v1(59.26,21.95) v1(59.39,40.8) v1(59.32,7.92) v1(59.31,6.09) v1(59.57,18.67) v1(59.63,37.98) v1(59.78,40.45) v1(59.75,21.9) v1(59.82,7.92) v1(59.81,6.09) v1(60,53) v1(60,51) v1(60,49) v1(60,47) v1(60,45) v1(60,43) v1(60,41) v1(59.99,37.56) v1(60,35) v1(60,33) v1(60,31) v1(60,29) v1(60,27) v1(60,25) v1(60,23) v1(60,17) v1(60,15) v1(60,13) v1(60,11) v1(60,9) v1(60,5) v1(60,3) v1(60,1) v1(60.07,18.39) v1(60.14,40.03) v1(60.16,21.72) v1(60.39,37.17) v1(60.32,7.92) v1(60.31,6.09) v1(60.54,39.64) v1(60.55,21.32) v1(60.52,18.04) v1(60.79,36.83) v1(60.82,7.92) v1(60.81,6.09) v1(60.95,39.3) v1(60.97,20.91) v1(60.9,17.63) v1(61,12.5) v1(61,12) v1(61,11.5) v1(61,11) v1(61,10.5) v1(61,3.5) v1(61,3) v1(61,2.5) v1(61,2) v1(61,1.5) v1(61.15,36.46) v1(61.31,38.88) v1(61.33,20.45) v1(61.32,7.92) v1(61.31,6.09) v1(61.48,17.4) v1(61.56,35.96) v1(61.5,12.5) v1(61.5,12) v1(61.5,11.5) v1(61.5,11) v1(61.5,10.5) v1(61.5,3.5) v1(61.5,3) v1(61.5,2.5) v1(61.5,2) v1(61.5,1.5) v1(61.71,38.49) v1(61.84,20.14) v1(61.82,7.92) v1(61.81,6.09) v1(62,53) v1(62,51) v1(62,49) v1(62,47) v1(62,45) v1(62,43) v1(62,41) v1(62,39) v1(62,33) v1(62,31) v1(62,29) v1(62,27) v1(62,25) v1(62,23) v1(62,21) v1(62,15) v1(62,13) v1(62,12.5) v1(62,12) v1(62,11.5) v1(62,11) v1(62,10.5) v1(62,9) v1(62,5) v1(62,3.5) v1(62,3) v1(62,2.5) v1(62,2) v1(62,1.5) v1(62.08,38.14) v1(62.02,35.56) v1(62.09,17.46) v1(62.35,20.02) v1(62.34,7.93) v1(62.34,6.08) v1(62.45,37.78) v1(62.43,35.14) v1(62.5,12.5) v1(62.5,12) v1(62.5,11.5) v1(62.5,11) v1(62.5,10.5) v1(62.5,3.5) v1(62.5,3) v1(62.5,2.5) v1(62.5,2) v1(62.5,1.5) v1(62.62,17.7) v1(62.79,19.68) v1(62.81,34.74) v1(62.84,7.93) v1(62.84,6.08) v1(62.92,37.37) v1(63,18.13) v1(63,12.5) v1(63,12) v1(63,11.5) v1(63,11) v1(63,10.5) v1(63,3.5) v1(63,3) v1(63,2.5) v1(63,2) v1(63,1.5) v1(63.14,19.15) v1(63.17,18.66) v1(63.23,34.37) v1(63.4,36.83) v1(63.34,7.93) v1(63.34,6.08) v1(63.5,12.5) v1(63.5,12) v1(63.5,11.5) v1(63.5,11) v1(63.5,10.5) v1(63.5,3.5) v1(63.5,3) v1(63.5,2.5) v1(63.5,2) v1(63.5,1.5) v1(63.61,33.92) v1(63.83,36.42) v1(63.84,7.93) v1(63.84,6.08) v1(64,53) v1(64,51) v1(64,49) v1(64,47) v1(64,45) v1(64,43) v1(64,41) v1(64,39) v1(64,37) v1(64,31) v1(64,29) v1(64,27) v1(64,25) v1(64,23) v1(64,21) v1(64,19) v1(64,17) v1(64,15) v1(64,13) v1(64,12.5) v1(64,12) v1(64,11.5) v1(64,11) v1(64,10.5) v1(64,9) v1(64,5) v1(64,3.5) v1(64,3) v1(64,2.5) v1(64,2) v1(64,1.5) v1(64.11,33.42) v1(64.21,35.99) v1(64.34,7.93) v1(64.34,6.08) v1(64.53,32.97) v1(64.5,12.5) v1(64.5,12) v1(64.5,11.5) v1(64.5,11) v1(64.5,10.5) v1(64.5,3.5) v1(64.5,3) v1(64.5,2.5) v1(64.5,2) v1(64.5,1.5) v1(64.63,35.61) v1(64.88,32.36) v1(64.84,7.93) v1(64.84,6.08) v1(65,12.5) v1(65,12) v1(65,11.5) v1(65,11) v1(65,10.5) v1(65,3.5) v1(65,3) v1(65,2.5) v1(65,2) v1(65,1.5) v1(65.12,35.23) v1(65.34,7.93) v1(65.34,6.08) v1(65.45,32.17) v1(65.5,12.5) v1(65.5,12) v1(65.5,11.5) v1(65.5,11) v1(65.5,10.5) v1(65.5,3.5) v1(65.5,3) v1(65.5,2.5) v1(65.5,2) v1(65.5,1.5) v1(65.63,34.92) v1(66,53) v1(66,51) v1(66,49) v1(66,47) v1(66,45) v1(66,43) v1(66,41) v1(66,39) v1(66,31) v1(66,29) v1(66,27) v1(66,25) v1(66,23) v1(66,21) v1(66,19) v1(66,17) v1(66,15) v1(66.18,32.19) v1(66.25,34.87) v1(66.79,34.51) v1(66.7,32.47) v1(67.11,34.03) v1(67.12,32.93) v1(67.24,33.48) v1(68,53) v1(68,51) v1(68,49) v1(68,47) v1(68,45) v1(68,43) v1(68,41) v1(68,39) v1(68,37) v1(68,35) v1(68,33) v1(68,31) v1(68,29) v1(68,27) v1(68,25) v1(68,23) v1(68,21) v1(68,19) v1(68,17) v1(68,15) v1(70,53) v1(70,51) v1(70,49) v1(70,47) v1(70,45) v1(70,43) v1(70,41) v1(70,39) v1(70,37) v1(70,35) v1(70,33) v1(70,31) v1(70,29) v1(70,27) v1(70,25) v1(70,23) v1(70,21) v1(70,19) v1(70,17) v1(70,15) v2(19.25,30.75) v2(19.25,30.25) v2(19.25,29.75) v2(19.25,29.25) v2(19.75,30.75) v2(19.75,30.25) v2(19.75,29.75) v2(19.75,29.25) v2(20.25,30.75) v2(20.25,30.25) v2(20.25,29.75) v2(20.25,29.25) v2(20.75,30.75) v2(20.75,30.25) v2(20.75,29.75) v2(20.75,29.25) v2(21.25,30.75)
VCC: length 48.9
  TOP w0.5: v1(23.84,19.51) 23.84,13.61 23.85,13.6 C4.2 23.85,12.3 23.84,12.29 P1.9 ; L1.1 C3.2 C18.2 20.25,35.35 ; 20.25,35.35 FB1.1 ; 20.25,35.35 v1(20.25,36.75)
  TOP w1: P1.9 P1.7 P1.5 P1.3 P1.1
  L3 w0.5: v1(20.25,36.75) 18.32,36.75 14.28,32.71 14.28,27.62 22.39,19.51 v1(23.84,19.51)
VCC_10: length 7.1
  TOP w0.2: U1.15 19.75,31.65 19.95,31.85 19.95,34.15 19.75,34.35 19.25,34.35 ; L2.1 C5.1
  TOP w0.5: C5.1 19.25,34.35 C2.1 FB1.2
VCC_CONT: length 21.9
  TOP w0.5: 13.68,6.39 10.67,6.39 P1.22 ; 13.68,6.39 18.78,6.39 ; 13.68,6.39 P1.18 ; 18.78,6.39 23.08,6.39 23.84,7.15 P1.10 ; 18.78,6.39 18.76,6.41 P1.14
ANT: length 10.6
  TOP w0.5: L6.1 C13.1 26.42,24.72 arc(27.22,24.19) 28.16,24 J3.1
ANT_9: length 3.3
  TOP w0.25: U1.9 21.58,29.25
  TOP w0.5: 23.12,28.05 22.42,28.75 C12.1 22.41,28.76 22.16,29.01 arc(21.9,29.19) 21.58,29.25 ; 23.12,28.05 22.76,27.69 C14.1 ; 23.12,28.05 L5.2
CPS: length 21.5
  TOP w0.25: U1.5 19.25,13.36 17.47,11.58 17.47,9.71 P1.16
CSD: length 26.3
  TOP w0.25: P1.20 12.47,9.79 12.47,11.47 13.36,12.36 17.35,12.36 18.75,13.76 U1.4
CTX: length 20.9
  TOP w0.25: P1.12 20.18,9.58 20.18,11.84 19.75,12.27 U1.6
PA_OUT: length 3.4
  TOP w0.2: 20.75,32.1 L1.2
  TOP w0.25: U1.13 20.75,31.63
  TOP w0.5: 20.75,31.63 20.75,32.1 ; L1.2 21.56,32.15 v1(22.05,32.65) 22.06,32.65 L3.2
RX: length 18.8
  TOP w0.25: U1.2 18.14,30.25
  TOP w0.5: 18.14,30.25 J1.1
TX: length 1.5
  TOP w0.25: U1.1 18.62,30.75 arc(18.43,30.79) 18.26,30.9
  TOP w0.5: 18.26,30.9 R1.1
TXALT: length 1.5
  TOP w0.25: U1.3 18.62,29.75 arc(18.43,29.71) 18.26,29.6
  TOP w0.5: 18.26,29.6 R2.1
N17610851: length 21.5
  TOP w0.5: J2.1 2.55,44.25 arc(4.73,43.82) 6.58,42.58 R1.2
N17610982: length 2.4
  TOP w0.25: L4.1 C7.1 C8.1 L3.1
N17611082: length 1.8
  TOP w0.25: U1.11 C9.1 L4.2
N17611094: length 2.9
  TOP w0.5: C14.2 23.47,26.99 23.86,27.38 ; 23.86,27.38 L5.1 ; 23.86,27.38 23.86,27.3 24.51,26.65 C10.1 24.96,26.19 24.96,26.18 L6.2
N17611136: length 0.5
  TOP w0.25: U1.7 U1.8
N17611154: length 0.7
  TOP w0.25: U1.16 L2.2
N17611175: length 21.5
  TOP w0.5: J5.1 2.55,16.25 arc(4.73,16.68) 6.58,17.92 R2.2
N17617542: length 21.5
  TOP w0.5: J6.1 49.55,47 arc(51.73,46.57) 53.58,45.33 R4.2
N17617544: length 18.8
  TOP w0.25: J10.1 65.22,7
  TOP w0.5: J7.1 65.22,7
N17617677: length 1.5
  TOP w0.25: v1(65.75,33.5) 65.62,33.5 arc(65.43,33.54) 65.26,33.65
  TOP w0.5: 65.26,33.65 R4.1
N17626822: length 2.9
  TOP w0.5: 59.14,20.62 59.53,21.01 L7.1 ; 59.14,20.62 C17.2 ; 59.14,20.62 59.14,20.7 58.49,21.35 C11.1 58.04,21.81 58.04,21.82 L8.2
N17626830: length 10.6
  TOP w0.5: L8.1 C16.1 56.58,23.28 arc(55.78,23.81) 54.84,24 J13.1
N17626834: length 3.7
  TOP w0.25: 61.42,18.75 v1(61.75,18.75)
  TOP w0.5: C15.1 60.59,19.24 60.84,18.99 ; C15.1 60.84,19 60.84,18.99 ; C15.1 60.58,19.25 59.88,19.95 ; 59.88,19.95 C17.1 ; 59.88,19.95 60.24,20.31 L7.2 ; 60.84,18.99 arc(61.1,18.81) 61.42,18.75

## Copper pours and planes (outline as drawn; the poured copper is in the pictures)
GND on BOTTOM (solid shape): 20.9,34.35 20.03,32.67 20.9,31 20.9,29.12 18.55,29.12 18.55,36.23 20.9,36.23
GND on BOTTOM (solid shape): 25.6,29.12 23.25,29.12 23.25,31 24.12,32.67 23.25,34.35 23.25,36.23 25.6,36.23
GND on BOTTOM (solid shape): 60.58,20.43 59.7,18.75 60.58,17.07 60.58,15.2 58.23,15.2 58.23,22.3 60.58,22.3
GND on BOTTOM (solid shape): 64.58,35.18 63.7,33.5 64.58,31.82 64.58,29.95 62.23,29.95 62.23,37.05 64.58,37.05
GND on BOTTOM (solid shape): 65.28,15.2 62.92,15.2 62.92,17.07 63.8,18.75 62.92,20.43 62.92,22.3 65.28,22.3
GND on BOTTOM (solid shape): 69.28,29.95 66.92,29.95 66.92,31.82 67.8,33.5 66.92,35.18 66.92,37.05 69.28,37.05
GND on TOP: 0,3 0,54 36,54 36,3 ; 4 cut-outs
GND on TOP: 47,0 47,54 71,54 71,14 65.75,14 65.75,0 ; 2 cut-outs
GND on BOTTOM, L3: 0,3 0,54 36,54 36,3
GND on BOTTOM, L3: 47,0 47,54 71,54 71,14 65.75,14 65.75,0
GND on L2: 0,3 0,15.38 0.25,15.38 0.25,17.12 0,17.12 0,29.38 0.25,29.38 0.25,31.12 0,31.12 0,43.38 0.25,43.38 0.25,45.12 0,45.12 0,54 36,54 36,24.88 35.75,24.88 35.75,23.12 36,23.12 36,3
GND on L2: 47,0 47,6.12 47.25,6.12 47.25,7.88 47,7.88 47,23.12 47.25,23.12 47.25,24.88 47,24.88 47,46.12 47.25,46.12 47.25,47.88 47,47.88 47,54 71,54 71,14 65.75,14 65.75,7.88 65.5,7.88 65.5,6.12 65.75,6.12 65.75,0

Small or netless copper shapes (teardrops, artwork), in the pictures only: 9 on TOP

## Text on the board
User.Comments: 2 | TOL:+-5% | CPW=.400 | W=0.500 | 50 OHM | NO SOLDERMASK OVER THE 50 ohms LINES(only L1). | C
Ref Des/Silkscreen Top: VCTL | N/C | CSD | GND | CPS | CTX | VCC | TX_ALT | TX | RX | SKYWORKS SOLUTIONS | Z1185-C | ANT | Z1185-C-CAL | TX/TX_ALT
User.26: 1    4
User.32: WHITE INK | TEST COUPON: 1 PER PANEL
User.45: FIGURE | SIZE | 0.15 | 0.2 | 0.25 | 1.016 | 1.42 | DRILL CHART: TOP to BOTTOM | ALL UNITS ARE IN MILLIMETERS | TOLERANCE | +0.075/-0.075 | +0.05/-0.05 | +0.0762/-0.0762 | PLATED | NON-PLATED | QTY | 1 | 17 | 1870 | 22 | 4
